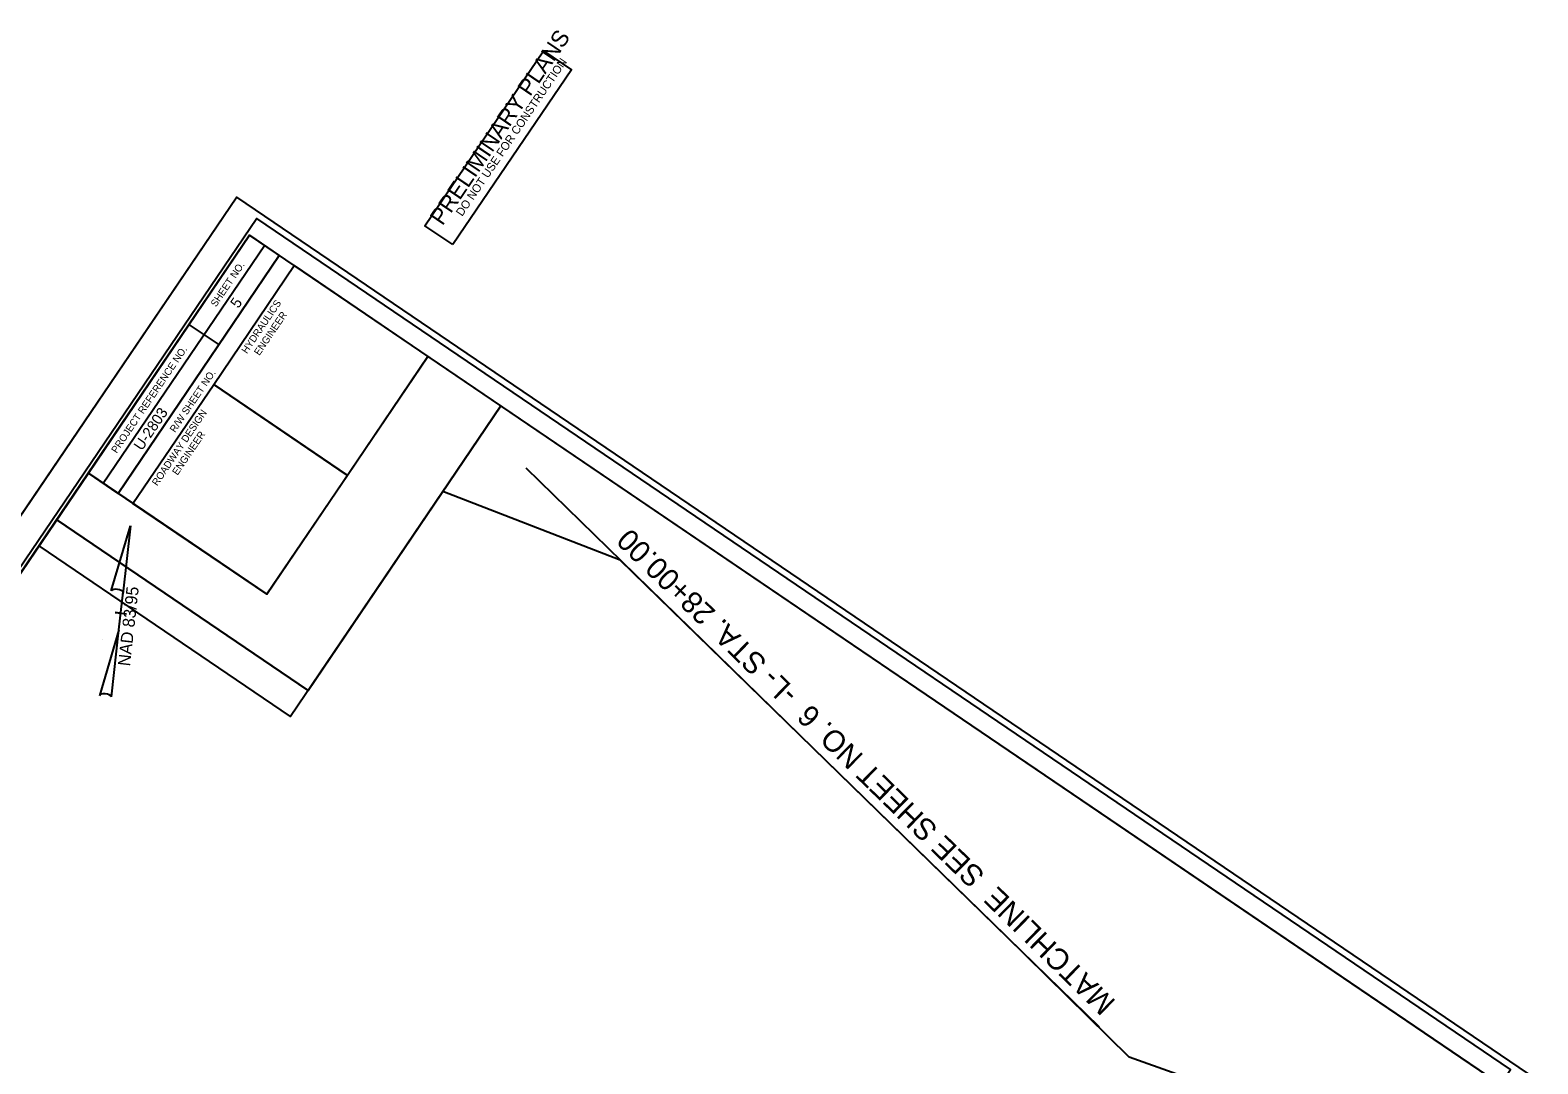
# Model space of a CAD drawing. Extents: x 1975407 to 1977258, y 778272 to 780396.
# Drawn here: x 1976209 to 1977258, y 779677 to 780396 of the extents above; entities that cross this region are included whole.
import ezdxf

# ---------------------------------------------------------------- set-up
doc = ezdxf.new("R2010")
doc.units = 0
for name, color, linetype in [('Matchline', 7, 'Continuous'), ('Matchline Text', 7, 'Continuous'), ('Old_Level_1', 7, 'Continuous'), ('Sheet Clip Boundary CELL', 7, 'Continuous'), ('Sheet Cutting Line CELL', 7, 'Continuous'), ('Sheet Data Field CELL', 7, 'Continuous'), ('Sheet North Arrow Point CELL', 7, 'Continuous'), ('Sheet Plan CELL', 7, 'Continuous'), ('Sheet Plan Layout CELL', 7, 'Continuous'), ('Sheet Plot Border Inside CELL', 7, 'Continuous'), ('Sheet Plot Border Outside CELL', 7, 'Continuous'), ('Sheet Sticker Preliminary CELL', 7, 'Continuous')]:
    doc.layers.add(name, color=color, linetype=linetype)

msp = doc.modelspace()

# ---------------------------------------------------------------- linework, layer by layer
at = {"layer": 'Matchline'}
msp.add_lwpolyline([(1976953.2, 779702.1), (1976753.8, 779896.4), (1976553.9, 780091.2)], dxfattribs=at)
at = {"layer": 'Old_Level_1'}
for p, q in [((1976265.1, 780005.9), (1976278.4, 780051)), ((1976278.5, 780051), (1976273.2, 780003.5)), ((1976278.5, 780051), (1976278.4, 780051)), ((1976278.5, 780051), (1976278.4, 780051)), ((1976270.4, 779978.8), (1976273.3, 780004.9)), ((1976273.2, 780003.5), (1976273.3, 780004.8)), ((1976271.2, 779990.4), (1976267.7, 779990.8)), ((1976267.7, 779990.8), (1976267.7, 779990.8)), ((1976267.8, 779990.8), (1976275.7, 779989.9)), ((1976270.4, 779978.8), (1976256.8, 779932.8)), ((1976265.2, 779932.1), (1976270.4, 779978.8))]:
    msp.add_line(p, q, dxfattribs=at)
for centre, start_param, end_param in [((1976269.2, 780004.9), 0.216388, 2.908219), ((1976261, 779932.2), 0.201328, 3.141593)]:
    msp.add_ellipse(centre, major_axis=(4.2, -0.5), ratio=0.461098, start_param=start_param, end_param=end_param, dxfattribs=at)
at = {"layer": 'Sheet Clip Boundary CELL'}
msp.add_lwpolyline([(1976497.2, 778583.1), (1977189.9, 779604.2), (1976973.8, 779681.3), (1976888, 779765.6), (1976619.5, 780027.3), (1976496, 780074.9), (1976389.8, 779918.3), (1976214.8, 780037.1), (1975535, 779035.2), (1975693.9, 778927.3), (1975738.3, 778974.2), (1975853.6, 778922.6), (1976185.1, 778747.3)], close=True, dxfattribs=at)
at = {"layer": 'Sheet Cutting Line CELL'}
msp.add_line((1976352.4, 780279.9), (1975407.2, 778886.8), dxfattribs=at)
at = {"layer": 'Sheet North Arrow Point CELL'}
msp.add_line((1976258.9, 779972.2), (1976258.9, 779972.2), dxfattribs=at)
at = {"layer": 'Sheet Plan CELL'}
for p, q in [((1976259.5, 780080.7), (1976371.8, 780246.2)), ((1976269.9, 780073.6), (1976382.1, 780239.2)), ((1976269.9, 780073.6), (1976382.1, 780239.2)), ((1976319.3, 780191.1), (1976340.1, 780177.1)), ((1976336.4, 780149.4), (1976429.4, 780086.3)), ((1976269.9, 780073.6), (1976280.2, 780066.6))]:
    msp.add_line(p, q, dxfattribs=at)
for points in [[(1976361.4, 780253.3), (1975519.3, 779012), (1976388.1, 778422.4), (1977230.3, 779663.7)], [(1976249.1, 780087.7), (1976361.4, 780253.3), (1976382.1, 780239.2), (1976269.9, 780073.6)], [(1976336.4, 780149.4), (1976392.5, 780232.2), (1976485.6, 780169), (1976429.5, 780086.2)], [(1976388.1, 778422.4), (1975519.3, 779011.9), (1976249.1, 780087.7), (1976373.3, 780003.5), (1976485.6, 780169), (1977230.3, 779663.7)], [(1976280.2, 780066.6), (1976336.4, 780149.4), (1976429.5, 780086.2), (1976373.3, 780003.5)]]:
    msp.add_lwpolyline(points, close=True, dxfattribs=at)
at = {"layer": 'Sheet Plan Layout CELL'}
for points in [[(1976402.1, 779936.5), (1976536.4, 780134.5), (1976361.4, 780253.3), (1976227.1, 780055.3)], [(1975519.3, 779011.9), (1976388.1, 778422.4), (1977230.3, 779663.7), (1976536.4, 780134.5), (1976402.1, 779936.5), (1976227.1, 780055.3)]]:
    msp.add_lwpolyline(points, close=True, dxfattribs=at)
at = {"layer": 'Sheet Plot Border Inside CELL'}
msp.add_lwpolyline([(1976304, 778294), (1977239.4, 779672.7), (1976366.4, 780265), (1975431, 778886.3)], close=True, dxfattribs=at)
at = {"layer": 'Sheet Plot Border Outside CELL'}
msp.add_lwpolyline([(1976313.3, 778272), (1977258.5, 779665.2), (1976352.4, 780279.9), (1975407.2, 778886.8)], close=True, dxfattribs=at)
at = {"layer": 'Sheet Sticker Preliminary CELL'}
msp.add_lwpolyline([(1976502.9, 780246.8), (1976483.5, 780260), (1976566, 780381.6), (1976585.5, 780368.4)], close=True, dxfattribs=at)

# ---------------------------------------------------------------- texts
at = {"layer": 'Matchline Text'}
msp.add_text('MATCHLINE  SEE SHEET NO. 6  -L- STA. 28+00.00', height=15, rotation=135.7395, dxfattribs=at).set_placement((1976965.2, 779720))
at = {"layer": 'Old_Level_1'}
msp.add_text('NAD 83/95', height=8.5, rotation=83.6101, dxfattribs=at).set_placement((1976278.1, 779953.1))
at = {"layer": 'Sheet Data Field CELL'}
for s, p in [('5  ', (1976353.6, 780202)), ('U-2803   ', (1976286.4, 780102.9))]:
    msp.add_text(s, height=7.5, rotation=55.8441, dxfattribs=at).set_placement(p)
at = {"layer": 'Sheet Plan CELL'}
for s, p in [('SHEET NO.', (1976338, 780203)), ('HYDRAULICS', (1976359.5, 780170.5)), ('ENGINEER', (1976368.2, 780169.2)), ('PROJECT REFERENCE NO.', (1976268.8, 780101.2)), ('R/W SHEET NO.', (1976309.5, 780115.6)), ('ROADWAY DESIGN', (1976297.1, 780078.5)), ('ENGINEER', (1976311.2, 780085.9))]:
    msp.add_text(s, height=5, rotation=55.8441, dxfattribs=at).set_placement(p)
at = {"layer": 'Sheet Sticker Preliminary CELL'}
for s, height, p in [('PRELIMINARY PLANS', 11.52, (1976495.7, 780259.5)), ('DO NOT USE FOR CONSTRUCTION', 5.76, (1976509.4, 780266.1))]:
    msp.add_text(s, height=height, rotation=55.8441, dxfattribs=at).set_placement(p)

doc.saveas('drawing.dxf')
